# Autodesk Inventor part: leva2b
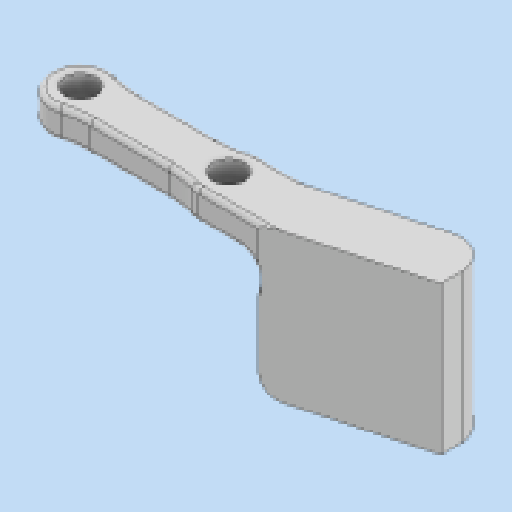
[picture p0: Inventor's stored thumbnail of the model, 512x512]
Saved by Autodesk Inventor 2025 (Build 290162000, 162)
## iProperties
Created: 2026-03
Part Number: leva2b
Material: Generico
Document SubType Name: Modeling
Designer: R5800u
Density: 1 g/cm^3
Appearance: Default
Author: R5800u
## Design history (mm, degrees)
sketch "Schizzo1"
  geometry: L1 (7.5, 2.5)-(-7.5, 2.5); L2 (-7.5, 2.5)-(-7.5, -2.5); L3 (-7.5, -2.5)-(7.5, -2.5); L4 (7.5, -2.5)-(7.5, 2.5); L5 (7.5, 2.5)-(-7.5, -2.5); L6 (-7.5, 2.5)-(7.5, -2.5); C1 r 3 at (7.5, 0); C2 r 3 at (-7.5, 0); 5 further points
  constraints: 12 end point, 4 midpoint, 2 centre point, 2 parallel, 1 horizontal, 1 perpendicular
  dimensions: "d0" = 15 distance of L3.end L2.end; "d1" = 5 distance of L2.end L1.end; "d4" = 6 diameter of C1; "d5" = 6 diameter of C2
extrude "Estrusione1" new body sketch "Schizzo1" distance "d2" = 3; taper "d3" = 0 deg
sketch "Schizzo2"
  geometry: A1 r 3 centre (7.5, 0) between (5.842, -2.5) and (5.842, 2.5) reference; A2 r 3 centre (-7.5, 0) between (-5.842, 2.5) and (-5.842, -2.5) reference; 3 further points
  constraints: 2 coincident
hole "Foro1" sketch "Schizzo2" at (7.5, 0), (-7.5, 0) diameter "d6" = 3.2; stored, may be unused: countersink angle "d10" = 90 deg, drill point angle "d12" = 118 deg; dims "d7" = 6, "d8" = 6.5, "d9" = 3.4, "d11" = 8
sketch "Schizzo3"
  geometry: L1 (5.842, 2.5)-(-5.842, 2.5) reference; L2 (-5.842, -2.5)-(5.842, -2.5) reference; L3 (7.5, 0)-(7.5, 3); L4 (7.5, 0)-(7.5, -3); L5 (7.5, 3)-(13.5, 3); L6 (13.5, 3)-(13.5, -3); L7 (13.5, -3)-(7.5, -3); L8 (7.5, -3)-(7.5, 3); L9 (13.5, -3)-(10.036, 3); C1 r 1.6 at (-7.5, 0) reference; C2 r 1.6 at (7.5, 0) reference; A1 r 3 centre (7.5, 0) between (5.842, -2.5) and (5.842, 2.5) reference; A2 r 3 centre (-7.5, 0) between (-5.842, 2.5) and (-5.842, -2.5) reference; 2 further points
  constraints: 14 end point, 3 point on line, 2 parallel, 2 point on circle, 1 horizontal, 1 perpendicular, 1 vertical
  dimensions: "d13" = 6 distance of L6.end L7.end; "d16" = 30 deg angle of L9 L6
extrude "Estrusione2" join sketch "Schizzo3" stored distance "d14" = 10; taper "d15" = 0 deg
fillet "Raccordo1" dims "d17" = 10
sketch "Schizzo7"
  geometry: L1 (13.5, -3)-(13.5, 3) reference; L2 (13.5, 3)-(16.5, -2.196); L3 (16.5, -2.196)-(13.5, -3); L4 (13.5, -3)-(16.098, -1.5); 1 further point
  constraints: 6 end point, 1 perpendicular, 1 point on line
  dimensions: "d30" = 6 distance of L1.end L2.end; "d31" = 30 deg angle of L2 L1
extrude "Estrusione6" join sketch "Schizzo7" stored distance "d32" = 10; taper "d33" = 0 deg
sketch "Schizzo8"
  geometry: L1 (13.5, 3)-(13.5, -3) reference; L2 (13.5, -3)-(27.964, 0.973); L3 (27.964, 0.973)-(27.964, 6.973); L4 (27.964, 6.973)-(13.5, 3); L5 (27.964, 3.973)-(13.5, 0); 1 further point
  constraints: 8 end point, 2 midpoint, 1 parallel
  dimensions: "d34" = 6 distance of L2.end L3.end; "d35" = 74.64 deg angle of L1 L2; "d36" = 15 distance of L5.start L5.end
extrude "Estrusione7" join sketch "Schizzo8" distance "d37" = 15; taper "d38" = 0 deg
chamfer "Smusso1" distance "d39" = 2; stored, may be unused: second distance "d40" = 2, angle "d41" = 45 deg
fillet "Raccordo2" dims "d42" = 2
fillet "Raccordo3" dims "d43" = 3
fillet "Raccordo4" dims "d44" = 0.5
fillet "Raccordo5" dims "d45" = 0.5
node "Solido1"
node "Linea chiusa proiettata1"
